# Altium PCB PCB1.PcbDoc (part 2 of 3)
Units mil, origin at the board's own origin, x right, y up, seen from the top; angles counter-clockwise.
Board outline 5995.03 x 3870.03 mil, 2 copper layers (Top Layer, Bottom Layer); 16 components, 23 nets, 121 pads, 0 vias.
Unrouted connection lines stored in the file: 7.
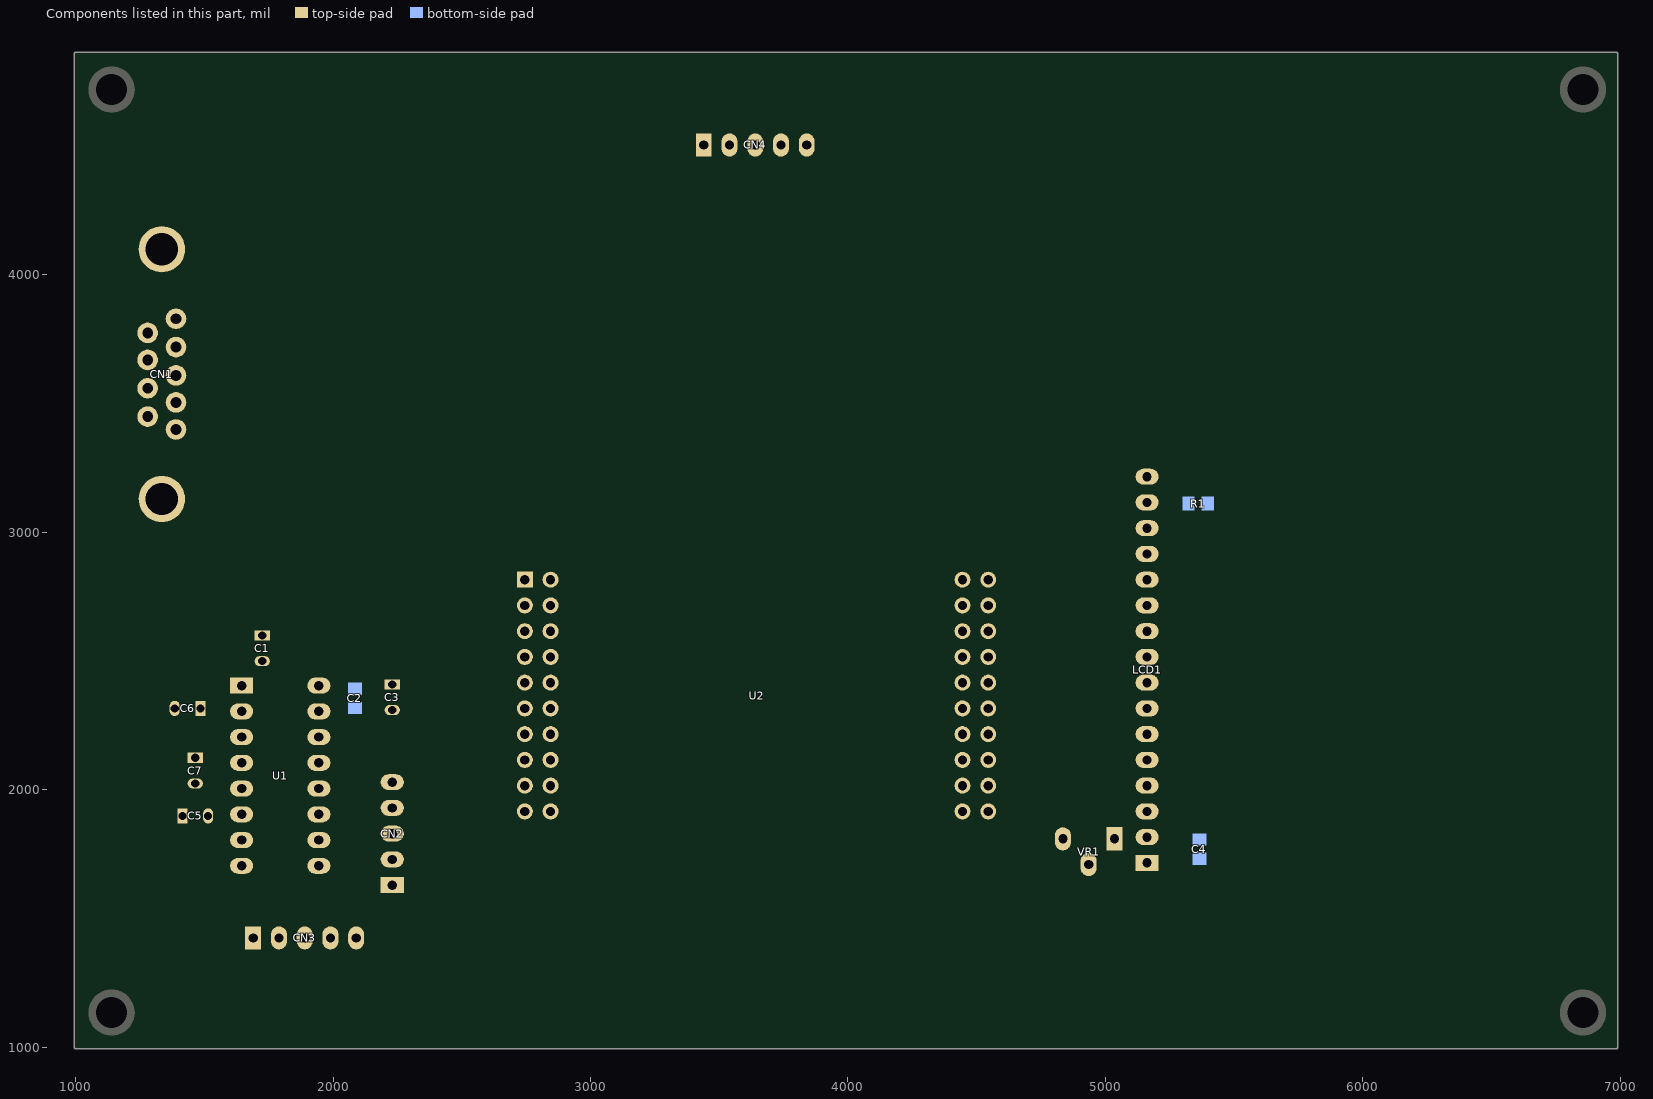
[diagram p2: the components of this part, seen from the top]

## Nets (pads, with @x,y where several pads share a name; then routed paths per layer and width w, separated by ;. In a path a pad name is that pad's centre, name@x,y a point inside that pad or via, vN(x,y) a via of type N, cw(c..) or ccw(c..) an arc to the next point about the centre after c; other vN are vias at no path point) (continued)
copper on no net: (continued)
  Bottom Layer w1: 1727,4165 2162,4165 ; 1727,4166 1944,4166 ; 1727,4167 1942,4167 ; 1727,4168 1940,4168 ; 1727,4169 1938,4169 ; 1727,4170 1937,4170 ; 1727,4171 1935,4171 ; 1727,4172 1933,4172 ; 1727,4173 1931,4173 ; 1727,4174 1930,4174 ; 1727,4175 1928,4175 ; 1727,4176 1926,4176 ; 1727,4177 1925,4177 ; 1727,4178 1923,4178 ; 1727,4179 1921,4179 ; 1727,4180 1919,4180 ; 1727,4181 1918,4181 ; 1727,4182 1916,4182 ; 1727,4183 1914,4183 ; 1727,4184 1912,4184 ; 1727,4185 1911,4185 ; 1727,4186 1909,4186 ; 1727,4187 1907,4187 ; 1727,4188 1905,4188 ; 1727,4189 1904,4189 ; 1727,4190 1902,4190 ; 1727,4191 1900,4191 ; 1727,4192 1899,4192 ; 1727,4193 1897,4193 ; 1727,4194 1895,4194 ; 1727,4195 1893,4195 ; 1727,4196 1892,4196 ; 1727,4197 1890,4197 ; 1727,4198 1888,4198 ; 1727,4199 1886,4199 ; 1727,4200 1885,4200 ; 1727,4201 1883,4201 ; 1727,4202 1881,4202 ; 1727,4203 1879,4203 ; 1727,4204 1878,4204 ; 1727,4205 1876,4205 ; 1727,4206 1874,4206 ; 1727,4207 1873,4207 ; 1727,4208 1871,4208 ; 1727,4209 1869,4209 ; 1727,4210 1867,4210 ; 1727,4211 1866,4211 ; 1727,4212 1864,4212 ; 1727,4213 1862,4213 ; 1727,4214 1860,4214 ; 1727,4215 1859,4215 ; 1727,4216 1857,4216 ; 1727,4217 1855,4217 ; 1727,4218 1854,4218 ; 1727,4219 1852,4219 ; 1727,4220 1850,4220 ; 1727,4221 1848,4221 ; 1727,4222 1847,4222 ; 1727,4223 1845,4223 ; 1727,4224 1843,4224 ; 1727,4225 1841,4225 ; 1727,4226 1840,4226 ; 1727,4227 1838,4227 ; 1727,4228 1837,4228 ; 1727,4229 1837,4229 ; 1727,4230 1837,4230 ; 1727,4231 1837,4231 ; 1727,4232 1837,4232 ; 1727,4233 1837,4233 ; 1727,4234 1837,4234 ; 1727,4235 1837,4235 ; 1727,4236 1837,4236 ; 1727,4237 1837,4237 ; 1727,4238 1837,4238 ; 1727,4239 1837,4239 ; 1727,4240 1837,4240 ; 1727,4241 1837,4241 ; 1727,4242 1837,4242 ; 1727,4243 1837,4243 ; 1727,4244 1837,4244 ; 1727,4245 1837,4245 ; 1727,4246 1837,4246 ; 1727,4247 1837,4247 ; 1727,4248 1837,4248 ; 1727,4249 1837,4249 ; 1727,4250 1837,4250 ; 1727,4251 1837,4251 ; 1727,4252 1837,4252 ; 1727,4253 1837,4253 ; 1727,4254 1837,4254 ; 1727,4255 1837,4255 ; 1727,4256 1837,4256 ; 1727,4257 1837,4257 ; 1727,4258 1837,4258 ; 1727,4259 1837,4259 ; 1727,4260 1837,4260 ; 1727,4261 1837,4261 ; 1727,4262 1837,4262 ; 1727,4263 1837,4263 ; 1727,4264 1837,4264 ; 1727,4265 1837,4265 ; 1727,4266 1837,4266 ; 1727,4267 1837,4267 ; 1727,4268 1837,4268 ; 1727,4269 1837,4269 ; 1727,4270 1837,4270 ; 1727,4271 1837,4271 ; 1727,4272 1837,4272 ; 1727,4273 1837,4273 ; 1727,4274 1837,4274 ; 1727,4275 1837,4275 ; 1727,4276 1837,4276 ; 1727,4277 1837,4277 ; 1727,4278 1837,4278 ; 1727,4279 1837,4279 ; 1727,4280 1837,4280 ; 1727,4281 1837,4281 ; 1727,4282 1837,4282 ; 1727,4283 1837,4283 ; 1727,4284 1837,4284 ; 1727,4285 1837,4285 ; 1727,4286 1837,4286 ; 1727,4287 1837,4287 ; 1727,4288 1837,4288 ; 1727,4289 1837,4289 ; 1727,4290 1837,4290 ; 1728,4164 2162,4164 ; 1729,4291 1837,4291 ; 1730,4163 1943,4163 ; 1730,4292 1837,4292 ; 1732,4162 1941,4162 ; 1732,4293 1837,4293 ; 1733,4161 1939,4161 ; 1734,4294 1837,4294 ; 1735,4160 1938,4160 ; 1735,4295 1837,4295 ; 1737,4159 1936,4159 ; 1737,4296 1837,4296 ; 1739,4158 1934,4158 ; 1739,4297 1837,4297 ; 1740,4157 1932,4157 ; 1741,4298 1837,4298 ; 1742,4156 1931,4156 ; 1742,4299 1837,4299 ; 1744,4155 1929,4155 ; 1744,4300 1837,4300 ; 1746,4154 1927,4154 ; 1746,4301 1837,4301 ; 1747,4153 1925,4153 ; 1748,4302 1837,4302 ; 1749,4152 1924,4152 ; 1749,4303 1837,4303 ; 1751,4151 1922,4151 ; 1751,4304 1837,4304 ; 1753,4150 1920,4150 ; 1753,4305 1837,4305 ; 1754,4149 1918,4149 ; 1754,4306 1837,4306 ; 1756,4148 1917,4148 ; 1756,4307 1837,4307 ; 1758,4147 1915,4147 ; 1758,4308 1837,4308 ; 1759,4146 1913,4146 ; 1760,4309 1837,4309 ; 1761,4145 1912,4145 ; 1761,4310 1837,4310 ; 1763,4144 1910,4144 ; 1763,4311 1837,4311 ; 1765,4143 1908,4143 ; 1765,4312 1837,4312 ; 1766,4142 1906,4142 ; 1767,4313 1837,4313 ; 1768,4141 1905,4141 ; 1768,4314 1837,4314 ; 1770,4140 1903,4140 ; 1770,4315 1837,4315 ; 1772,4139 1901,4139 ; 1772,4316 1837,4316 ; 1773,4138 1899,4138 ; 1774,4317 1837,4317 ; 1775,4137 1898,4137 ; 1775,4318 1837,4318 ; 1777,4136 1896,4136 ; 1777,4319 1837,4319 ; 1779,4135 1894,4135 ; 1779,4320 1837,4320 ; 1780,4134 1892,4134 ; 1780,4321 1837,4321 ; 1782,4133 1891,4133 ; 1782,4322 1837,4322 ; 1784,4132 1889,4132 ; 1784,4323 1837,4323 ; 1785,4131 1887,4131 ; 1786,4324 1837,4324 ; 1787,4130 1886,4130 ; 1787,4325 1837,4325 ; 1789,4129 1884,4129 ; 1789,4326 1837,4326 ; 1791,4128 1882,4128 ; 1791,4327 1837,4327 ; 1792,4127 1880,4127 ; 1793,4328 1837,4328 ; 1794,4126 1879,4126 ; 1794,4329 1837,4329 ; 1796,4125 1877,4125 ; 1796,4330 1837,4330 ; 1798,4124 1875,4124 ; 1798,4331 1837,4331 ; 1799,4123 1873,4123 ; 1800,4332 1837,4332 ; 1801,4122 1872,4122 ; 1801,4333 1837,4333 ; 1803,4121 1870,4121 ; 1803,4334 1837,4334 ; 1804,4120 1868,4120 ; 1805,4335 1837,4335 ; 1806,4119 1866,4119 ; 1806,4336 1837,4336 ; 1808,4118 1865,4118 ; 1808,4337 1837,4337 ; 1810,4117 1863,4117 ; 1810,4338 1837,4338 ; 1811,4116 1861,4116 ; 1812,4339 1837,4339 ; 1813,4115 1860,4115 ; 1813,4340 1837,4340 ; 1815,4114 1858,4114 ; 1815,4341 1837,4341 ; 1817,4113 1856,4113 ; 1817,4342 1837,4342 ; 1818,4112 1854,4112 ; 1819,4343 1837,4343 ; 1820,4111 1853,4111 ; 1820,4344 1837,4344 ; 1822,4110 1851,4110 ; 1822,4345 1837,4345 ; 1824,4109 1849,4109 ; 1824,4346 1837,4346 ; 1825,4108 1847,4108 ; 1825,4347 1837,4347 ; 1827,4107 1846,4107 ; 1827,4348 1837,4348 ; 1829,4106 1844,4106 ; 1829,4349 1837,4349 ; 1830,4105 1842,4105 ; 1831,4350 1837,4350 ; 1832,4104 1840,4104 ; 1832,4351 1837,4351 ; 1834,4103 1839,4103 ; 1834,4352 1837,4352 ; 1836,4102 1837,4102 ; 1836,4353 1838,4353 ; 1836,4354 1839,4354 ; 1836,4355 1841,4355 ; 1836,4356 1843,4356 ; 1836,4357 1844,4357 ; 1836,4358 1846,4358 ; 1836,4359 1848,4359 ; 1836,4360 1850,4360 ; 1836,4361 1851,4361 ; 1836,4362 1853,4362 ; 1836,4363 1855,4363 ; 1836,4364 1857,4364 ; 1836,4365 1858,4365 ; 1836,4366 1860,4366 ; 1836,4367 1862,4367 ; 1836,4368 1864,4368 ; 1836,4369 1865,4369 ; 1836,4370 1867,4370 ; 1836,4371 1869,4371 ; 1836,4372 1870,4372 ; 1836,4373 1872,4373 ; 1836,4374 1874,4374 ; 1836,4375 1876,4375 ; 1836,4376 1877,4376 ; 1836,4377 1879,4377 ; 1836,4378 1881,4378 ; 1836,4379 1883,4379 ; 1836,4380 1884,4380 ; 1836,4381 1886,4381 ; 1836,4382 1888,4382 ; 1836,4383 1889,4383 ; 1836,4384 1891,4384 ; 1836,4385 1893,4385 ; 1836,4386 1895,4386 ; 1836,4387 1896,4387 ; 1836,4388 1898,4388 ; 1836,4389 1900,4389 ; 1836,4390 1902,4390 ; 1836,4391 1903,4391 ; 1836,4392 1905,4392 ; 1836,4393 1907,4393 ; 1836,4394 1909,4394 ; 1836,4395 1910,4395 ; 1836,4396 1912,4396 ; 1836,4397 1914,4397 ; 1836,4398 1915,4398 ; 1836,4399 1917,4399 ; 1836,4400 1919,4400 ; 1836,4401 1921,4401 ; 1836,4402 1922,4402 ; 1836,4403 1924,4403 ; 1836,4404 1926,4404 ; 1836,4405 1928,4405 ; 1836,4406 1929,4406 ; 1836,4407 1931,4407 ; 1836,4408 1933,4408 ; 1836,4409 1935,4409 ; 1836,4410 1936,4410 ; 1836,4411 1938,4411 ; 1836,4412 1940,4412 ; 1836,4413 1941,4413 ; 1836,4414 1943,4414 ; 1836,4415 2054,4415 ; 1836,4416 2054,4416 ; 1836,4417 2054,4417 ; 1836,4418 2054,4418 ; 1836,4419 2054,4419 ; 1836,4420 2054,4420 ; 1836,4421 2054,4421 ; 1836,4422 2054,4422 ; 1836,4423 2054,4423 ; 1836,4424 2054,4424 ; 1836,4425 2054,4425 ; 1836,4426 2054,4426 ; 1836,4427 2054,4427 ; 1836,4428 2054,4428 ; 1836,4429 2054,4429 ; 1836,4430 2054,4430 ; 1836,4431 2054,4431 ; 1836,4432 2054,4432 ; 1836,4433 2054,4433 ; 1836,4434 2054,4434 ; 1836,4435 2054,4435 ; 1836,4436 2054,4436 ; 1836,4437 2054,4437 ; 1836,4438 2054,4438 ; 1836,4439 2054,4439 ; 1836,4440 2054,4440 ; 1836,4441 2054,4441 ; 1836,4442 2054,4442 ; 1836,4443 2054,4443 ; 1836,4444 2054,4444 ; 1836,4445 2054,4445 ; 1836,4446 2054,4446 ; 1836,4447 2054,4447 ; 1836,4448 2054,4448 ; 1836,4449 2054,4449 ; 1836,4450 2054,4450 ; 1836,4451 2054,4451 ; 1836,4452 2054,4452 ; 1836,4453 2054,4453 ; 1836,4454 2054,4454 ; 1836,4455 2054,4455 ; 1836,4456 2054,4456 ; 1836,4457 2054,4457 ; 1836,4458 2054,4458 ; 1836,4459 2054,4459 ; 1836,4460 2054,4460 ; 1836,4461 2054,4461 ; 1836,4462 2054,4462 ; 1836,4463 2054,4463 ; 1836,4464 2054,4464 ; 1836,4465 2054,4465 ; 1836,4466 2054,4466 ; 1836,4467 2054,4467 ; 1836,4468 2054,4468 ; 1836,4469 2054,4469 ; 1836,4470 2054,4470 ; 1836,4471 2054,4471 ; 1836,4472 2054,4472 ; 1836,4473 2054,4473 ; 1836,4474 2054,4474 ; 1836,4475 2054,4475 ; 1836,4476 2054,4476 ; 1836,4477 2054,4477 ; 1836,4478 2054,4478 ; 1837,4479 2053,4479 ; 1839,4480 2051,4480 ; 1840,4481 2049,4481 ; 1842,4482 2048,4482 ; 1844,4483 2046,4483 ; 1846,4484 2044,4484 ; 1847,4485 2042,4485 ; 1849,4486 2041,4486 ; 1851,4487 2039,4487 ; 1853,4488 2037,4488 ; 1854,4489 2036,4489 ; 1856,4490 2034,4490 ; 1858,4491 2032,4491 ; 1860,4492 2030,4492 ; 1861,4493 2029,4493 ; 1863,4494 2027,4494 ; 1865,4273 1886,4273 ; 1865,4274 1887,4274 ; 1865,4275 1887,4275 ; 1865,4495 2025,4495 ; 1866,4276 1888,4276 ; 1866,4354 1889,4354 ; 1866,4496 2023,4496 ; 1867,4228 1874,4228 ; 1867,4229 1874,4229 ; 1867,4230 1874,4230 ; 1867,4231 1874,4231 ; 1867,4232 1874,4232 ; 1867,4233 1874,4233 ; 1867,4234 1874,4234 ; 1867,4235 1874,4235 ; 1867,4236 1874,4236 ; 1867,4237 1874,4237 ; 1867,4238 1874,4238 ; 1867,4239 1874,4239 ; 1867,4240 1874,4240 ; 1867,4241 1874,4241 ; 1867,4242 1874,4242 ; 1867,4243 1874,4243 ; 1867,4244 1874,4244 ; 1867,4245 1874,4245 ; 1867,4246 1874,4246 ; 1867,4247 1881,4247 ; 1867,4248 1880,4248 ; 1867,4249 1880,4249 ; 1867,4250 1880,4250 ; 1867,4251 1880,4251 ; 1867,4252 1879,4252 ; 1867,4253 1879,4253 ; 1867,4254 1879,4254 ; 1867,4255 1878,4255 ; 1867,4256 1878,4256 ; 1867,4257 1878,4257 ; 1867,4258 1878,4258 ; 1867,4277 1888,4277 ; 1867,4278 1889,4278 ; 1867,4353 1890,4353 ; 1868,4259 1877,4259 ; 1868,4279 1889,4279 ; 1868,4352 1890,4352 ; 1868,4497 2022,4497 ; 1869,4280 1890,4280 ; 1869,4281 1891,4281 ; 1869,4351 1891,4351 ; 1870,4282 1891,4282 ; 1870,4350 1892,4350 ; 1870,4498 2020,4498 ; 1871,4283 1892,4283 ; 1871,4284 1892,4284 ; 1871,4349 1893,4349 ; 1872,4285 1893,4285 ; 1872,4286 1893,4286 ; 1872,4348 1894,4348 ; 1872,4499 2018,4499 ; 1873,4287 1894,4287 ; 1873,4346 1896,4346 ; 1873,4347 1895,4347 ; 1873,4500 2016,4500 ; 1874,4288 1895,4288 ; 1874,4289 1895,4289 ; 1874,4345 1897,4345 ; 1875,4243 1882,4243 ; 1875,4244 1881,4244 ; 1875,4245 1881,4245 ; 1875,4246 1881,4246 ; 1875,4290 1896,4290 ; 1875,4344 1898,4344 ; 1875,4501 2015,4501 ; 1876,4239 1889,4239 ; 1876,4240 1882,4240 ; 1876,4241 1882,4241 ; 1876,4242 1882,4242 ; 1876,4291 1896,4291 ; 1876,4292 1897,4292 ; 1876,4343 1899,4343 ; 1877,4235 1888,4235 ; 1877,4236 1888,4236 ; 1877,4237 1888,4237 ; 1877,4238 1889,4238 ; 1877,4293 1897,4293 ; 1877,4342 1899,4342 ; 1877,4502 2013,4502 ; 1878,4231 1887,4231 ; 1878,4232 1887,4232 ; 1878,4233 1887,4233 ; 1878,4234 1888,4234 ; 1878,4294 1898,4294 ; 1878,4295 1899,4295 ; 1878,4341 1900,4341 ; 1879,4228 1886,4228 ; 1879,4229 1886,4229 ; 1879,4230 1887,4230 ; 1879,4296 1899,4296 ; 1879,4340 1901,4340 ; 1879,4503 2011,4503 ; 1880,4297 1900,4297 ; 1880,4298 1900,4298 ; 1880,4339 1902,4339 ; 1880,4504 2010,4504 ; 1881,4299 1901,4299 ; 1881,4300 1902,4300 ; 1881,4338 1903,4338 ; 1882,4301 1902,4301 ; 1882,4337 1904,4337 ; 1882,4505 2008,4505 ; 1883,4240 1889,4240 ; 1883,4241 1889,4241 ; 1883,4242 1890,4242 ; 1883,4302 1903,4302 ; 1883,4303 1903,4303 ; 1883,4336 1905,4336 ; 1884,4243 1890,4243 ; 1884,4244 1890,4244 ; 1884,4245 1890,4245 ; 1884,4246 1890,4246 ; 1884,4304 1904,4304 ; 1884,4335 1906,4335 ; 1884,4506 2006,4506 ; 1885,4247 1898,4247 ; 1885,4248 1898,4248 ; 1885,4249 1898,4249 ; 1885,4250 1898,4250 ; 1885,4305 1904,4305 ; 1885,4306 1905,4306 ; 1885,4334 1907,4334 ; 1886,4251 1898,4251 ; 1886,4252 1898,4252 ; 1886,4253 1898,4253 ; 1886,4254 1898,4254 ; 1886,4307 1906,4307 ; 1886,4333 1908,4333 ; 1886,4507 2004,4507 ; 1887,4255 1898,4255 ; 1887,4256 1898,4256 ; 1887,4257 1898,4257 ; 1887,4308 1906,4308 ; 1887,4309 1907,4309 ; 1887,4332 1908,4332 ; 1887,4508 2003,4508 ; 1888,4258 1898,4258 ; 1888,4259 1898,4259 ; 1888,4310 1907,4310 ; 1888,4311 1937,4311 ; 1888,4331 1909,4331 ; 1889,4312 1937,4312 ; 1889,4330 1910,4330 ; 1889,4509 2001,4509 ; 1890,4313 1937,4313 ; 1890,4314 1937,4314 ; 1890,4329 1911,4329 ; 1891,4228 1898,4228 ; 1891,4229 1898,4229 ; 1891,4230 1898,4230 ; 1891,4231 1898,4231 ; 1891,4232 1898,4232 ; 1891,4233 1898,4233 ; 1891,4234 1898,4234 ; 1891,4235 1898,4235 ; 1891,4236 1898,4236 ; 1891,4237 1898,4237 ; 1891,4238 1898,4238 ; 1891,4239 1898,4239 ; 1891,4240 1898,4240 ; 1891,4241 1898,4241 ; 1891,4242 1898,4242 ; 1891,4243 1898,4243 ; 1891,4244 1898,4244 ; 1891,4245 1898,4245 ; 1891,4246 1898,4246 ; 1891,4315 1937,4315 ; 1891,4328 1912,4328 ; 1891,4510 1999,4510 ; 1892,4316 1937,4316 ; 1892,4317 1937,4317 ; 1892,4326 1914,4326 ; 1892,4327 1913,4327 ; 1892,4511 1997,4511 ; 1893,4318 1937,4318 ; 1893,4325 1915,4325 ; 1894,4319 1937,4319 ; 1894,4320 1919,4320 ; 1894,4324 1916,4324 ; 1894,4512 1996,4512 ; 1895,4321 1918,4321 ; 1895,4323 1917,4323 ; 1896,4322 1918,4322 ; 1896,4513 1994,4513 ; 1898,4514 1992,4514 ; 1899,4515 1991,4515 ; 1901,4516 1989,4516 ; 1902,4237 1910,4237 ; 1903,4235 1911,4235 ; 1903,4236 1910,4236 ; 1903,4238 1910,4238 ; 1903,4250 1910,4250 ; 1903,4251 1910,4251 ; 1903,4252 1911,4252 ; 1903,4253 1913,4253 ; 1903,4517 1987,4517 ; 1904,4233 1927,4233 ; 1904,4234 1913,4234 ; 1904,4254 1927,4254 ; 1905,4232 1926,4232 ; 1905,4255 1926,4255 ; 1905,4256 1925,4256 ; 1905,4518 1985,4518 ; 1906,4231 1925,4231 ; 1906,4239 1909,4239 ; 1906,4257 1924,4257 ; 1906,4519 1984,4519 ; 1907,4230 1924,4230 ; 1907,4249 1909,4249 ; 1908,4229 1923,4229 ; 1908,4258 1922,4258 ; 1908,4310 1937,4310 ; 1908,4520 1982,4520 ; 1909,4309 1937,4309 ; 1910,4228 1921,4228 ; 1910,4259 1920,4259 ; 1910,4308 1937,4308 ; 1910,4521 1980,4521 ; 1911,4307 1937,4307 ; 1911,4522 1978,4522 ; 1912,4306 1937,4306 ; 1913,4305 1937,4305 ; 1913,4523 1977,4523 ; 1914,4304 1937,4304 ; 1915,4303 1937,4303 ; 1915,4524 1975,4524 ; 1916,4302 1937,4302 ; 1917,4301 1937,4301 ; 1917,4525 1973,4525 ; 1918,4253 1928,4253 ; 1918,4299 1937,4299 ; 1918,4300 1937,4300 ; 1918,4526 1971,4526 ; 1919,4234 1928,4234 ; 1919,4298 1937,4298 ; 1920,4235 1928,4235 ; 1920,4252 1928,4252 ; 1920,4273 1937,4273 ; 1920,4274 1937,4274 ; 1920,4275 1937,4275 ; 1920,4276 1937,4276 ; 1920,4277 1937,4277 ; 1920,4278 1937,4278 ; 1920,4279 1937,4279 ; 1920,4280 1937,4280 ; 1920,4281 1937,4281 ; 1920,4282 1937,4282 ; 1920,4283 1937,4283 ; 1920,4284 1937,4284 ; 1920,4285 1937,4285 ; 1920,4286 1937,4286 ; 1920,4287 1937,4287 ; 1920,4288 1937,4288 ; 1920,4289 1937,4289 ; 1920,4290 1937,4290 ; 1920,4291 1937,4291 ; 1920,4292 1937,4292 ; 1920,4293 1937,4293 ; 1920,4294 1937,4294 ; 1920,4295 1937,4295 ; 1920,4296 1937,4296 ; 1920,4297 1937,4297 ; 1920,4320 1937,4320 ; 1920,4321 1937,4321 ; 1920,4322 1937,4322 ; 1920,4323 1937,4323 ; 1920,4324 1937,4324 ; 1920,4325 1937,4325 ; 1920,4326 1937,4326 ; 1920,4327 1937,4327 ; 1920,4328 1937,4328 ; 1920,4329 1937,4329 ; 1920,4330 1937,4330 ; 1920,4331 1937,4331 ; 1920,4332 1937,4332 ; 1920,4333 1937,4333 ; 1920,4334 1937,4334 ; 1920,4335 1937,4335 ; 1920,4336 1937,4336 ; 1920,4337 1937,4337 ; 1920,4338 1937,4338 ; 1920,4339 1937,4339 ; 1920,4340 1937,4340 ; 1920,4341 1937,4341 ; 1920,4342 1937,4342 ; 1920,4343 1937,4343 ; 1920,4344 1937,4344 ; 1920,4345 1937,4345 ; 1920,4346 1937,4346 ; 1920,4347 1937,4347 ; 1920,4348 1937,4348 ; 1920,4349 1937,4349 ; 1920,4350 1937,4350 ; 1920,4351 1937,4351 ; 1920,4352 1937,4352 ; 1920,4353 1937,4353 ; 1920,4354 1937,4354 ; 1920,4527 1970,4527 ; 1921,4236 1929,4236 ; 1921,4251 1929,4251 ; 1922,4237 1929,4237 ; 1922,4238 1929,4238 ; 1922,4239 1930,4239 ; 1922,4240 1930,4240 ; 1922,4247 1930,4247 ; 1922,4248 1930,4248 ; 1922,4249 1929,4249 ; 1922,4250 1929,4250 ; 1922,4528 1968,4528 ; 1923,4241 1930,4241 ; 1923,4242 1930,4242 ; 1923,4243 1930,4243 ; 1923,4244 1930,4244 ; 1923,4245 1930,4245 ; 1923,4246 1930,4246 ; 1924,4529 1966,4529 ; 1925,4530 1965,4530 ; 1927,4531 1963,4531 ; 1929,4532 1961,4532 ; 1931,4533 1959,4533 ; 1932,4534 1958,4534 ; 1934,4229 1942,4229 ; 1934,4230 1942,4230 ; 1934,4231 1942,4231 ; 1934,4232 1942,4232 ; 1934,4233 1942,4233 ; 1934,4234 1942,4234 ; 1934,4235 1942,4235 ; 1934,4236 1942,4236 ; 1934,4237 1942,4237 ; 1934,4238 1942,4238 ; 1934,4239 1942,4239 ; 1934,4240 1941,4240 ; 1934,4241 1942,4241 ; 1934,4242 1960,4242 ; 1934,4243 1960,4243 ; 1934,4244 1960,4244 ; 1934,4245 1960,4245 ; 1934,4246 1960,4246 ; 1934,4247 1960,4247 ; 1934,4248 1941,4248 ; 1934,4249 1942,4249 ; 1934,4250 1942,4250 ; 1934,4251 1942,4251 ; 1934,4252 1942,4252 ; 1934,4253 1942,4253 ; 1934,4254 1942,4254 ; 1934,4255 1942,4255 ; 1934,4256 1942,4256 ; 1934,4257 1942,4257 ; 1934,4258 1942,4258 ; 1934,4535 1956,4535 ; 1935,4228 1941,4228 ; 1935,4259 1941,4259 ; 1936,4536 1954,4536 ; 1937,4537 1952,4537 ; 1939,4538 1951,4538 ; 1941,4539 1949,4539 ; 1943,4540 1947,4540 ; 1944,4541 1946,4541 ; 1946,4166 2162,4166 ; 1947,4163 2160,4163 ; 1947,4414 2054,4414 ; 1948,4167 2162,4167 ; 1948,4413 2054,4413 ; 1949,4162 2158,4162 ; 1950,4168 2162,4168 ; 1950,4292 1969,4292 ; 1950,4293 1968,4293 ; 1950,4294 1968,4294 ; 1950,4295 1968,4295 ; 1950,4296 1968,4296 ; 1950,4297 1967,4297 ; 1950,4298 1967,4298 ; 1950,4299 1968,4299 ; 1950,4300 1968,4300 ; 1950,4301 1968,4301 ; 1950,4412 2054,4412 ; 1951,4161 2156,4161 ; 1951,4169 2162,4169 ; 1951,4288 1974,4288 ; 1951,4289 1972,4289 ; 1951,4290 1970,4290 ; 1951,4291 1969,4291 ; 1951,4302 1968,4302 ; 1951,4303 1969,4303 ; 1951,4304 1970,4304 ; 1952,4160 2155,4160 ; 1952,4286 2018,4286 ; 1952,4287 2018,4287 ; 1952,4305 1971,4305 ; 1952,4306 1972,4306 ; 1952,4411 2054,4411 ; 1953,4170 2162,4170 ; 1953,4228 1960,4228 ; 1953,4229 1960,4229 ; 1953,4230 1960,4230 ; 1953,4231 1960,4231 ; 1953,4232 1960,4232 ; 1953,4233 1960,4233 ; 1953,4234 1960,4234 ; 1953,4235 1960,4235 ; 1953,4236 1960,4236 ; 1953,4237 1960,4237 ; 1953,4238 1960,4238 ; 1953,4239 1960,4239 ; 1953,4240 1960,4240 ; 1953,4241 1960,4241 ; 1953,4248 1960,4248 ; 1953,4249 1960,4249 ; 1953,4250 1960,4250 ; 1953,4251 1960,4251 ; 1953,4252 1960,4252 ; 1953,4253 1960,4253 ; 1953,4254 1960,4254 ; 1953,4255 1960,4255 ; 1953,4256 1960,4256 ; 1953,4257 1960,4257 ; 1953,4258 1960,4258 ; 1953,4259 1960,4259 ; 1953,4284 2018,4284 ; 1953,4285 2018,4285 ; 1953,4307 1975,4307 ; 1953,4308 2018,4308 ; 1954,4159 2153,4159 ; 1954,4283 2018,4283 ; 1954,4309 2018,4309 ; 1954,4329 1971,4329 ; 1954,4330 1970,4330 ; 1954,4331 1970,4331 ; 1954,4332 1970,4332 ; 1954,4333 1970,4333 ; 1954,4334 1971,4334 ; 1954,4335 1971,4335 ; 1954,4336 1971,4336 ; 1954,4337 1972,4337 ; 1954,4338 1973,4338 ; 1954,4410 2054,4410 ; 1955,4171 2162,4171 ; 1955,4281 2018,4281 ; 1955,4282 2018,4282 ; 1955,4310 2018,4310 ; 1955,4326 1972,4326 ; 1955,4327 1971,4327 ; 1955,4328 1971,4328 ; 1955,4339 1975,4339 ; 1955,4340 1979,4340 ; 1955,4341 2018,4341 ; 1955,4409 2054,4409 ; 1956,4158 2151,4158 ; 1956,4280 2018,4280 ; 1956,4311 2018,4311 ; 1956,4324 1974,4324 ; 1956,4325 1973,4325 ; 1956,4342 2018,4342 ; 1956,4343 2018,4343 ; 1957,4172 2162,4172 ; 1957,4279 2018,4279 ; 1957,4312 2018,4312 ; 1957,4323 1977,4323 ; 1957,4344 2018,4344 ; 1957,4345 2018,4345 ; 1957,4408 2054,4408 ; 1958,4157 2149,4157 ; 1958,4173 2162,4173 ; 1958,4278 2018,4278 ; 1958,4313 2018,4313 ; 1958,4321 2018,4321 ; 1958,4322 2018,4322 ; 1958,4346 2018,4346 ; 1959,4156 2148,4156 ; 1959,4320 2018,4320 ; 1959,4347 2018,4347 ; 1959,4407 2054,4407 ; 1960,4174 2162,4174 ; 1960,4277 2018,4277 ; 1960,4314 2018,4314 ; 1960,4319 2018,4319 ; 1960,4348 2018,4348 ; 1961,4155 2146,4155 ; 1961,4276 2018,4276 ; 1961,4315 2018,4315 ; 1961,4349 2018,4349 ; 1961,4406 2054,4406 ; 1962,4175 2162,4175 ; 1962,4318 2018,4318 ; 1962,4350 2018,4350 ; 1962,4405 2054,4405 ; 1963,4154 2144,4154 ; 1963,4275 2018,4275 ; 1963,4317 2018,4317 ; 1964,4153 2143,4153 ; 1964,4176 2162,4176 ; 1964,4316 2018,4316 ; 1964,4351 2018,4351 ; 1964,4404 2054,4404 ; 1965,4177 2162,4177 ; 1965,4228 1972,4228 ; 1965,4229 1972,4229 ; 1965,4230 1972,4230 ; 1965,4231 1972,4231 ; 1965,4232 1972,4232 ; 1965,4233 1972,4233 ; 1965,4234 1972,4234 ; 1965,4352 2018,4352 ; 1966,4152 2141,4152 ; 1966,4274 2018,4274 ; 1966,4403 2054,4403 ; 1967,4178 2162,4178 ; 1967,4402 2054,4402 ; 1968,4151 2139,4151 ; 1968,4353 2018,4353 ; 1969,4179 2162,4179 ; 1969,4401 2054,4401 ; 1970,4150 2137,4150 ; 1970,4180 2162,4180 ; 1971,4149 2136,4149 ; 1971,4245 1995,4245 ; 1971,4246 1980,4246 ; 1971,4247 1979,4247 ; 1971,4248 1978,4248 ; 1971,4249 1978,4249 ; 1971,4250 1978,4250 ; 1971,4251 1978,4251 ; 1971,4252 1979,4252 ; 1971,4253 1981,4253 ; 1971,4400 2054,4400 ; 1972,4181 2162,4181 ; 1972,4244 1995,4244 ; 1972,4254 1995,4254 ; 1972,4255 1995,4255 ; 1972,4273 2017,4273 ; 1972,4354 2017,4354 ; 1973,4148 2134,4148 ; 1973,4243 1995,4243 ; 1973,4256 1995,4256 ; 1973,4399 2054,4399 ; 1974,4182 2162,4182 ; 1974,4242 1995,4242 ; 1974,4257 1995,4257 ; 1974,4398 2054,4398 ; 1975,4147 2132,4147 ; 1975,4241 1995,4241 ; 1975,4258 1995,4258 ; 1976,4183 2162,4183 ; 1976,4397 2054,4397 ; 1977,4146 2130,4146 ; 1977,4184 2162,4184 ; 1977,4240 1995,4240 ; 1978,4145 2129,4145 ; 1978,4259 1995,4259 ; 1978,4396 2054,4396 ; 1979,4185 2162,4185 ; 1980,4144 2127,4144 ; 1980,4395 2054,4395 ; 1981,4186 2162,4186 ; 1981,4394 2054,4394 ; 1982,4143 2125,4143 ; 1983,4142 2123,4142 ; 1983,4187 2162,4187 ; 1983,4393 2054,4393 ; 1984,4188 2162,4188 ; 1985,4141 2122,4141 ; 1985,4392 2054,4392 ; 1986,4189 2162,4189 ; 1986,4391 2054,4391 ; 1987,4140 2120,4140 ; 1988,4190 2162,4190 ; 1988,4228 1995,4228 ; 1988,4229 1995,4229 ; 1988,4230 1995,4230 ; 1988,4231 1995,4231 ; 1988,4232 1995,4232 ; 1988,4233 1995,4233 ; 1988,4234 1995,4234 ; 1988,4235 1995,4235 ; 1988,4236 1995,4236 ; 1988,4237 1995,4237 ; 1988,4238 1995,4238 ; 1988,4239 1995,4239 ; 1988,4246 1995,4246 ; 1988,4247 1995,4247 ; 1988,4248 1995,4248 ; 1988,4249 1995,4249 ; 1988,4250 1995,4250 ; 1988,4251 1995,4251 ; 1988,4252 1995,4252 ; 1988,4253 1995,4253 ; 1988,4390 2054,4390 ; 1989,4139 2118,4139 ; 1990,4138 2117,4138 ; 1990,4191 2162,4191 ; 1990,4389 2054,4389 ; 1991,4192 2162,4192 ; 1992,4137 2115,4137 ; 1992,4388 2054,4388 ; 1993,4193 2162,4193 ; 1993,4387 2054,4387 ; 1994,4136 2113,4136 ; 1995,4194 2162,4194 ; 1995,4386 2054,4386 ; 1996,4135 2111,4135 ; 1996,4195 2162,4195 ; 1997,4134 2110,4134 ; 1997,4385 2054,4385 ; 1998,4196 2162,4196 ; 1998,4254 2023,4254 ; 1998,4255 2024,4255 ; 1998,4256 2024,4256 ; 1998,4257 2024,4257 ; 1998,4258 2024,4258 ; 1998,4259 2023,4259 ; 1999,4133 2108,4133 ; 1999,4384 2054,4384 ; 2000,4197 2162,4197 ; 2000,4383 2054,4383 ; 2001,4132 2106,4132 ; 2001,4288 2018,4288 ; 2001,4289 2018,4289 ; 2001,4290 2018,4290 ; 2001,4291 2018,4291 ; 2001,4292 2018,4292 ; 2001,4293 2018,4293 ; 2001,4294 2018,4294 ; 2001,4295 2018,4295 ; 2001,4296 2018,4296 ; 2001,4297 2018,4297 ; 2001,4298 2018,4298 ; 2001,4299 2018,4299 ; 2001,4300 2018,4300 ; 2001,4301 2018,4301 ; 2001,4302 2018,4302 ; 2001,4303 2018,4303 ; 2001,4304 2018,4304 ; 2001,4305 2018,4305 ; 2001,4306 2018,4306 ; 2001,4307 2018,4307 ; 2001,4323 2018,4323 ; 2001,4324 2018,4324 ; 2001,4325 2018,4325 ; 2001,4326 2018,4326 ; 2001,4327 2018,4327 ; 2001,4328 2018,4328 ; 2001,4329 2018,4329 ; 2001,4330 2018,4330 ; 2001,4331 2018,4331 ; 2001,4332 2018,4332 ; 2001,4333 2018,4333 ; 2001,4334 2018,4334 ; 2001,4335 2018,4335 ; 2001,4336 2018,4336 ; 2001,4337 2018,4337 ; 2001,4338 2018,4338 ; 2001,4339 2018,4339 ; 2001,4340 2018,4340 ; 2002,4198 2162,4198 ; 2002,4382 2054,4382 ; 2003,4131 2104,4131 ; 2003,4199 2162,4199 ; 2004,4130 2103,4130 ; 2004,4381 2054,4381 ; 2005,4200 2162,4200 ; 2006,4129 2101,4129 ; 2006,4380 2054,4380 ; 2007,4201 2162,4201 ; 2007,4229 2014,4229 ; 2007,4230 2014,4230 ; 2007,4231 2014,4231 ; 2007,4232 2014,4232 ; 2007,4233 2014,4233 ; 2007,4234 2014,4234 ; 2007,4235 2014,4235 ; 2007,4236 2014,4236 ; 2007,4237 2014,4237 ; 2007,4238 2014,4238 ; 2007,4239 2014,4239 ; 2007,4240 2014,4240 ; 2007,4241 2014,4241 ; 2007,4242 2014,4242 ; 2007,4243 2014,4243 ; 2007,4244 2014,4244 ; 2007,4245 2014,4245 ; 2007,4246 2014,4246 ; 2007,4247 2014,4247 ; 2007,4248 2014,4248 ; 2007,4249 2014,4249 ; 2007,4250 2014,4250 ; 2007,4251 2014,4251 ; 2007,4252 2014,4252 ; 2007,4253 2014,4253 ; 2007,4379 2054,4379 ; 2008,4128 2099,4128 ; 2008,4228 2014,4228 ; 2009,4127 2098,4127 ; 2009,4202 2162,4202 ; 2009,4378 2054,4378 ; 2010,4203 2162,4203 ; 2011,4126 2096,4126 ; 2011,4377 2054,4377 ; 2012,4204 2162,4204 ; 2012,4376 2054,4376 ; 2013,4125 2094,4125 ; 2014,4205 2162,4205 ; 2014,4375 2054,4375 ; 2015,4124 2092,4124 ; 2016,4123 2091,4123 ; 2016,4206 2162,4206 ; 2016,4374 2054,4374 ; 2017,4207 2162,4207 ; 2018,4122 2089,4122 ; 2018,4373 2054,4373 ; 2019,4208 2162,4208 ; 2019,4372 2054,4372 ; 2020,4121 2087,4121 ; 2021,4209 2162,4209 ; 2021,4371 2054,4371 ; 2022,4120 2085,4120 ; 2022,4210 2162,4210 ; 2023,4119 2084,4119 ; 2023,4370 2054,4370 ; 2024,4211 2162,4211 ; 2025,4118 2082,4118 ; 2025,4369 2054,4369 ; 2026,4212 2162,4212 ; 2026,4368 2054,4368 ; 2027,4117 2080,4117 ; 2028,4213 2162,4213 ; 2028,4367 2054,4367 ; 2029,4116 2078,4116 ; 2029,4214 2162,4214 ; 2030,4115 2077,4115 ; 2030,4366 2054,4366 ; 2031,4215 2162,4215 ; 2032,4114 2075,4114 ; 2032,4365 2054,4365 ; 2033,4216 2162,4216 ; 2033,4364 2054,4364 ; 2034,4113 2073,4113 ; 2035,4112 2072,4112 ; 2035,4217 2162,4217 ; 2035,4363 2054,4363 ; 2036,4218 2162,4218 ; 2037,4111 2070,4111 ; 2037,4362 2054,4362 ; 2038,4219 2162,4219 ; 2038,4361 2054,4361 ; 2039,4110 2068,4110 ; 2040,4220 2162,4220 ; 2040,4360 2054,4360 ; 2041,4109 2066,4109 ; 2042,4108 2065,4108 ; 2042,4221 2162,4221 ; 2042,4359 2054,4359 ; 2043,4222 2162,4222 ; 2044,4107 2063,4107 ; 2044,4358 2054,4358 ; 2045,4223 2162,4223 ; 2045,4357 2054,4357 ; 2046,4106 2061,4106 ; 2047,4224 2162,4224 ; 2047,4356 2054,4356 ; 2048,4105 2059,4105 ; 2048,4225 2162,4225 ; 2049,4104 2058,4104 ; 2049,4355 2054,4355 ; 2050,4226 2162,4226 ; 2051,4103 2056,4103 ; 2051,4354 2054,4354 ; 2052,4227 2162,4227 ; 2052,4353 2054,4353 ; 2053,4102 2054,4102 ; 2053,4228 2162,4228 ; 2053,4229 2162,4229 ; 2053,4230 2162,4230 ; 2053,4231 2162,4231 ; 2053,4232 2162,4232 ; 2053,4233 2162,4233 ; 2053,4234 2162,4234 ; 2053,4235 2162,4235 ; 2053,4236 2162,4236 ; 2053,4237 2162,4237 ; 2053,4238 2162,4238 ; 2053,4239 2162,4239 ; 2053,4240 2162,4240 ; 2053,4241 2162,4241 ; 2053,4242 2162,4242 ; 2053,4243 2162,4243 ; 2053,4244 2162,4244 ; 2053,4245 2162,4245 ; 2053,4246 2162,4246 ; 2053,4247 2162,4247 ; 2053,4248 2162,4248 ; 2053,4249 2162,4249 ; 2053,4250 2162,4250 ; 2053,4251 2162,4251 ; 2053,4252 2162,4252 ; 2053,4253 2162,4253 ; 2053,4254 2162,4254 ; 2053,4255 2162,4255 ; 2053,4256 2162,4256 ; 2053,4257 2162,4257 ; 2053,4258 2162,4258 ; 2053,4259 2162,4259 ; 2053,4260 2162,4260 ; 2053,4261 2162,4261 ; 2053,4262 2162,4262 ; 2053,4263 2162,4263 ; 2053,4264 2162,4264 ; 2053,4265 2162,4265 ; 2053,4266 2162,4266 ; 2053,4267 2162,4267 ; 2053,4268 2162,4268 ; 2053,4269 2162,4269 ; 2053,4270 2162,4270 ; 2053,4271 2162,4271 ; 2053,4272 2162,4272 ; 2053,4273 2162,4273 ; 2053,4274 2162,4274 ; 2053,4275 2162,4275 ; 2053,4276 2162,4276 ; 2053,4277 2162,4277 ; 2053,4278 2162,4278 ; 2053,4279 2162,4279 ; 2053,4280 2162,4280 ; 2053,4281 2162,4281 ; 2053,4282 2162,4282 ; 2053,4283 2162,4283 ; 2053,4284 2162,4284 ; 2053,4285 2162,4285 ; 2053,4286 2162,4286 ; 2053,4287 2162,4287 ; 2053,4288 2162,4288 ; 2053,4289 2162,4289 ; 2053,4290 2162,4290 ; 2053,4291 2161,4291 ; 2053,4292 2160,4292 ; 2053,4293 2158,4293 ; 2053,4294 2156,4294 ; 2053,4295 2154,4295 ; 2053,4296 2153,4296 ; 2053,4297 2151,4297 ; 2053,4298 2149,4298 ; 2053,4299 2147,4299 ; 2053,4300 2146,4300 ; 2053,4301 2144,4301 ; 2053,4302 2142,4302 ; 2053,4303 2141,4303 ; 2053,4304 2139,4304 ; 2053,4305 2137,4305 ; 2053,4306 2135,4306 ; 2053,4307 2134,4307 ; 2053,4308 2132,4308 ; 2053,4309 2130,4309 ; 2053,4310 2128,4310 ; 2053,4311 2127,4311 ; 2053,4312 2125,4312 ; 2053,4313 2123,4313 ; 2053,4314 2121,4314 ; 2053,4315 2120,4315 ; 2053,4316 2118,4316 ; 2053,4317 2116,4317 ; 2053,4318 2115,4318 ; 2053,4319 2113,4319 ; 2053,4320 2111,4320 ; 2053,4321 2109,4321 ; 2053,4322 2108,4322 ; 2053,4323 2106,4323 ; 2053,4324 2104,4324 ; 2053,4325 2102,4325 ; 2053,4326 2101,4326 ; 2053,4327 2099,4327 ; 2053,4328 2097,4328 ; 2053,4329 2095,4329 ; 2053,4330 2094,4330 ; 2053,4331 2092,4331 ; 2053,4332 2090,4332 ; 2053,4333 2089,4333 ; 2053,4334 2087,4334 ; 2053,4335 2085,4335 ; 2053,4336 2083,4336 ; 2053,4337 2082,4337 ; 2053,4338 2080,4338 ; 2053,4339 2078,4339 ; 2053,4340 2076,4340 ; 2053,4341 2075,4341 ; 2053,4342 2073,4342 ; 2053,4343 2071,4343 ; 2053,4344 2070,4344 ; 2053,4345 2068,4345 ; 2053,4346 2066,4346 ; 2053,4347 2064,4347 ; 2053,4348 2063,4348 ; 2053,4349 2061,4349 ; 2053,4350 2059,4350 ; 2053,4351 2057,4351 ; 2053,4352 2056,4352 ; 6584,3319 6584,3856 ; 6585,3319 6585,3862 ; 6586,3319 6586,3865 ; 6587,3319 6587,3868 ; 6588,3319 6588,3871 ; 6589,3319 6589,3873 ; 6590,3319 6590,3875 ; 6591,3319 6591,3877 ; 6592,3319 6592,3879 ; 6593,3319 6593,3881 ; 6594,3319 6594,3882 ; 6595,3319 6595,3884 ; 6596,3319 6596,3885 ; 6597,3319 6597,3886 ; 6598,3319 6598,3887 ; 6599,3319 6599,3889 ; 6600,3319 6600,3890 ; 6601,3319 6601,3891 ; 6602,3319 6602,3892 ; 6603,3319 6603,3893 ; 6604,3319 6604,3894 ; 6605,3319 6605,3894 ; 6606,3319 6606,3895 ; 6607,3319 6607,3896 ; 6608,3319 6608,3897 ; 6609,3319 6609,3898 ; 6610,3319 6610,3898 ; 6611,3319 6611,3899 ; 6612,3319 6612,3900 ; 6613,3319 6613,3901 ; 6614,3319 6614,3901 ; 6615,3319 6615,3902 ; 6616,3319 6616,3902 ; 6617,3319 6617,3903 ; 6618,3319 6618,3904 ; 6619,3319 6619,3904 ; 6620,3319 6620,3904 ; 6621,3319 6621,3905 ; 6622,3319 6622,3905 ; 6623,3319 6623,3906 ; 6624,3319 6624,3906 ; 6625,3319 6625,3907 ; 6626,3319 6626,3907 ; 6627,3319 6627,3907 ; 6628,3319 6628,3908 ; 6629,3319 6629,3908 ; 6630,3319 6630,3908 ; 6631,3319 6631,3908 ; 6632,3319 6632,3909 ; 6633,3319 6633,3695 ; 6633,3726 6633,3764 ; 6633,3785 6633,3909 ; 6634,3319 6634,3650 ; 6634,3681 6634,3696 ; 6634,3727 6634,3764 ; 6634,3791 6634,3909 ; 6635,3319 6635,3651 ; 6635,3681 6635,3696 ; 6635,3727 6635,3764 ; 6635,3794 6635,3909 ; 6636,3319 6636,3651 ; 6636,3682 6636,3696 ; 6636,3727 6636,3764 ; 6636,3797 6636,3909 ; 6637,3319 6637,3651 ; 6637,3682 6637,3696 ; 6637,3727 6637,3764 ; 6637,3799 6637,3909 ; 6638,3319 6638,3651 ; 6638,3682 6638,3697 ; 6638,3728 6638,3764 ; 6638,3801 6638,3909 ; 6639,3319 6639,3652 ; 6639,3682 6639,3697 ; 6639,3728 6639,3764 ; 6639,3803 6639,3909 ; 6640,3319 6640,3652 ; 6640,3683 6640,3697 ; 6640,3728 6640,3763 ; 6640,3804 6640,3909 ; 6641,3319 6641,3652 ; 6641,3683 6641,3697 ; 6641,3728 6641,3763 ; 6641,3806 6641,3909 ; 6642,3319 6642,3652 ; 6642,3683 6642,3698 ; 6642,3729 6642,3763 ; 6642,3807 6642,3909 ; 6643,3319 6643,3653 ; 6643,3683 6643,3698 ; 6643,3729 6643,3763 ; 6643,3808 6643,3909 ; 6644,3319 6644,3653 ; 6644,3684 6644,3698 ; 6644,3729 6644,3763 ; 6644,3809 6644,3909 ; 6645,3319 6645,3653 ; 6645,3684 6645,3698 ; 6645,3729 6645,3763 ; 6645,3810 6645,3909 ; 6646,3319 6646,3653 ; 6646,3684 6646,3699 ; 6646,3730 6646,3763 ; 6646,3811 6646,3909 ; 6647,3319 6647,3654 ; 6647,3684 6647,3699 ; 6647,3730 6647,3763 ; 6647,3812 6647,3909 ; 6648,3319 6648,3654 ; 6648,3685 6648,3699 ; 6648,3730 6648,3763 ; 6648,3813 6648,3909 ; 6649,3319 6649,3654 ; 6649,3685 6649,3699 ; 6649,3730 6649,3763 ; 6649,3814 6649,3909 ; 6650,3319 6650,3655 ; 6650,3685 6650,3700 ; 6650,3731 6650,3763 ; 6650,3815 6650,3909 ; 6651,3319 6651,3655 ; 6651,3685 6651,3700 ; 6651,3731 6651,3763 ; 6651,3815 6651,3909 ; 6652,3319 6652,3655 ; 6652,3686 6652,3700 ; 6652,3731 6652,3763 ; 6652,3816 6652,3909 ; 6653,3319 6653,3655 ; 6653,3686 6653,3700 ; 6653,3731 6653,3763 ; 6653,3817 6653,3909 ; 6654,3319 6654,3656 ; 6654,3686 6654,3701 ; 6654,3731 6654,3763 ; 6654,3817 6654,3909 ; 6655,3319 6655,3656 ; 6655,3686 6655,3701 ; 6655,3732 6655,3763 ; 6655,3818 6655,3909 ; 6656,3319 6656,3656 ; 6656,3687 6656,3701 ; 6656,3732 6656,3763 ; 6656,3818 6656,3909 ; 6657,3319 6657,3386 ; 6657,3396 6657,3433 ; 6657,3444 6657,3656 ; 6657,3687 6657,3701 ; 6657,3732 6657,3763 ; 6657,3819 6657,3909 ; 6658,3319 6658,3381 ; 6658,3402 6658,3429 ; 6658,3450 6658,3657 ; 6658,3687 6658,3702 ; 6658,3732 6658,3763 ; 6658,3819 6658,3909 ; 6659,3319 6659,3379 ; 6659,3405 6659,3426 ; 6659,3453 6659,3644 ; 6659,3687 6659,3702 ; 6659,3733 6659,3763 ; 6659,3820 6659,3909 ; 6660,3319 6660,3377 ; 6660,3407 6660,3425 ; 6660,3455 6660,3464 ; 6660,3495 6660,3510 ; 6660,3541 6660,3558 ; 6660,3589 6660,3602 ; 6660,3633 6660,3644 ; 6660,3688 6660,3702 ; 6660,3733 6660,3763 ; 6660,3791 6660,3792 ; 6660,3820 6660,3909 ; 6661,3319 6661,3375 ; 6661,3409 6661,3423 ; 6661,3457 6661,3464 ; 6661,3495 6661,3510 ; 6661,3541 6661,3558 ; 6661,3589 6661,3603 ; 6661,3633 6661,3645 ; 6661,3688 6661,3702 ; 6661,3733 6661,3763 ; 6661,3791 6661,3792 ; 6661,3821 6661,3909 ; 6662,3319 6662,3374 ; 6662,3411 6662,3422 ; 6662,3458 6662,3464 ; 6662,3495 6662,3510 ; 6662,3541 6662,3558 ; 6662,3589 6662,3603 ; 6662,3634 6662,3645 ; 6662,3688 6662,3703 ; 6662,3733 6662,3763 ; 6662,3791 6662,3793 ; 6662,3821 6662,3909 ; 6663,3319 6663,3373 ; 6663,3413 6663,3422 ; 6663,3460 6663,3465 ; 6663,3496 6663,3511 ; 6663,3541 6663,3559 ; 6663,3589 6663,3603 ; 6663,3634 6663,3645 ; 6663,3688 6663,3703 ; 6663,3734 6663,3763 ; 6663,3791 6663,3793 ; 6663,3822 6663,3909 ; 6664,3319 6664,3373 ; 6664,3414 6664,3421 ; 6664,3461 6664,3465 ; 6664,3496 6664,3511 ; 6664,3542 6664,3559 ; 6664,3590 6664,3603 ; 6664,3634 6664,3645 ; 6664,3689 6664,3703 ; 6664,3734 6664,3763 ; 6664,3791 6664,3794 ; 6664,3822 6664,3909 ; 6665,3319 6665,3372 ; 6665,3415 6665,3420 ; 6665,3462 6665,3465 ; 6665,3496 6665,3511 ; 6665,3542 6665,3559 ; 6665,3590 6665,3604 ; 6665,3634 6665,3646 ; 6665,3689 6665,3704 ; 6665,3734 6665,3763 ; 6665,3791 6665,3794 ; 6665,3823 6665,3909 ; 6666,3319 6666,3372 ; 6666,3416 6666,3420 ; 6666,3463 6666,3465 ; 6666,3496 6666,3511 ; 6666,3542 6666,3559 ; 6666,3590 6666,3604 ; 6666,3635 6666,3646 ; 6666,3689 6666,3704 ; 6666,3734 6666,3762 ; 6666,3791 6666,3795 ; 6666,3824 6666,3909 ; 6667,3319 6667,3372 ; 6667,3417 6667,3420 ; 6667,3464 6667,3466 ; 6667,3497 6667,3512 ; 6667,3542 6667,3560 ; 6667,3590 6667,3604 ; 6667,3635 6667,3646 ; 6667,3689 6667,3704 ; 6667,3735 6667,3762 ; 6667,3791 6667,3795 ; 6667,3824 6667,3909 ; 6668,3319 6668,3372 ; 6668,3418 6668,3419 ; 6668,3465 6668,3466 ; 6668,3497 6668,3512 ; 6668,3543 6668,3560 ; 6668,3591 6668,3604 ; 6668,3635 6668,3646 ; 6668,3690 6668,3704 ; 6668,3735 6668,3762 ; 6668,3791 6668,3796 ; 6668,3825 6668,3909 ; 6669,3319 6669,3371 ; 6669,3497 6669,3512 ; 6669,3543 6669,3560 ; 6669,3591 6669,3605 ; 6669,3635 6669,3647 ; 6669,3690 6669,3705 ; 6669,3735 6669,3762 ; 6669,3791 6669,3796 ; 6669,3825 6669,3909 ; 6670,3319 6670,3371 ; 6670,3497 6670,3512 ; 6670,3543 6670,3560 ; 6670,3591 6670,3605 ; 6670,3636 6670,3647 ; 6670,3690 6670,3705 ; 6670,3735 6670,3762 ; 6670,3791 6670,3797 ; 6670,3826 6670,3909 ; 6671,3319 6671,3371 ; 6671,3498 6671,3513 ; 6671,3543 6671,3561 ; 6671,3591 6671,3605 ; 6671,3636 6671,3647 ; 6671,3690 6671,3705 ; 6671,3736 6671,3762 ; 6671,3791 6671,3797 ; 6671,3826 6671,3909 ; 6672,3319 6672,3371 ; 6672,3498 6672,3513 ; 6672,3544 6672,3561 ; 6672,3592 6672,3605 ; 6672,3636 6672,3647 ; 6672,3691 6672,3705 ; 6672,3736 6672,3762 ; 6672,3791 6672,3797 ; 6672,3827 6672,3909 ; 6673,3319 6673,3371 ; 6673,3498 6673,3513 ; 6673,3544 6673,3561 ; 6673,3592 6673,3606 ; 6673,3636 6673,3648 ; 6673,3691 6673,3706 ; 6673,3736 6673,3762 ; 6673,3791 6673,3798 ; 6673,3827 6673,3909 ; 6674,3319 6674,3371 ; 6674,3498 6674,3513 ; 6674,3544 6674,3561 ; 6674,3592 6674,3606 ; 6674,3637 6674,3648 ; 6674,3691 6674,3706 ; 6674,3736 6674,3762 ; 6674,3791 6674,3798 ; 6674,3828 6674,3909 ; 6675,3319 6675,3372 ; 6675,3499 6675,3514 ; 6675,3544 6675,3562 ; 6675,3592 6675,3606 ; 6675,3637 6675,3648 ; 6675,3691 6675,3706 ; 6675,3737 6675,3762 ; 6675,3791 6675,3799 ; 6675,3828 6675,3909 ; 6676,3319 6676,3372 ; 6676,3499 6676,3514 ; 6676,3545 6676,3562 ; 6676,3593 6676,3606 ; 6676,3637 6676,3648 ; 6676,3692 6676,3706 ; 6676,3737 6676,3762 ; 6676,3791 6676,3799 ; 6676,3829 6676,3909 ; 6677,3319 6677,3372 ; 6677,3499 6677,3514 ; 6677,3545 6677,3562 ; 6677,3593 6677,3607 ; 6677,3637 6677,3649 ; 6677,3692 6677,3707 ; 6677,3737 6677,3762 ; 6677,3792 6677,3800 ; 6677,3829 6677,3909 ; 6678,3319 6678,3372 ; 6678,3407 6678,3416 ; 6678,3455 6678,3464 ; 6678,3499 6678,3514 ; 6678,3545 6678,3562 ; 6678,3593 6678,3607 ; 6678,3638 6678,3662 ; 6678,3692 6678,3707 ; 6678,3737 6678,3762 ; 6678,3792 6678,3800 ; 6678,3830 6678,3909 ; 6679,3319 6679,3372 ; 6679,3406 6679,3418 ; 6679,3454 6679,3466 ; 6679,3500 6679,3515 ; 6679,3545 6679,3563 ; 6679,3593 6679,3607 ; 6679,3638 6679,3662 ; 6679,3692 6679,3707 ; 6679,3738 6679,3762 ; 6679,3792 6679,3801 ; 6679,3831 6679,3909 ; 6680,3319 6680,3373 ; 6680,3405 6680,3419 ; 6680,3453 6680,3467 ; 6680,3500 6680,3515 ; 6680,3546 6680,3563 ; 6680,3594 6680,3607 ; 6680,3638 6680,3662 ; 6680,3693 6680,3707 ; 6680,3738 6680,3762 ; 6680,3792 6680,3801 ; 6680,3831 6680,3909 ; 6681,3319 6681,3373 ; 6681,3405 6681,3420 ; 6681,3453 6681,3468 ; 6681,3500 6681,3515 ; 6681,3546 6681,3563 ; 6681,3594 6681,3608 ; 6681,3638 6681,3662 ; 6681,3693 6681,3708 ; 6681,3738 6681,3762 ; 6681,3792 6681,3802 ; 6681,3832 6681,3909 ; 6682,3319 6682,3373 ; 6682,3405 6682,3421 ; 6682,3453 6682,3469 ; 6682,3500 6682,3515 ; 6682,3546 6682,3563 ; 6682,3594 6682,3608 ; 6682,3639 6682,3663 ; 6682,3693 6682,3708 ; 6682,3738 6682,3762 ; 6682,3792 6682,3802 ; 6682,3832 6682,3909 ; 6683,3319 6683,3373 ; 6683,3404 6683,3421 ; 6683,3453 6683,3469 ; 6683,3501 6683,3516 ; 6683,3546 6683,3564 ; 6683,3594 6683,3608 ; 6683,3639 6683,3663 ; 6683,3693 6683,3708 ; 6683,3739 6683,3762 ; 6683,3792 6683,3802 ; 6683,3833 6683,3909 ; 6684,3319 6684,3374 ; 6684,3405 6684,3422 ; 6684,3453 6684,3470 ; 6684,3501 6684,3516 ; 6684,3547 6684,3564 ; 6684,3595 6684,3608 ; 6684,3639 6684,3663 ; 6684,3694 6684,3708 ; 6684,3739 6684,3762 ; 6684,3792 6684,3803 ; 6684,3833 6684,3909 ; 6685,3319 6685,3374 ; 6685,3405 6685,3422 ; 6685,3453 6685,3470 ; 6685,3501 6685,3516 ; 6685,3547 6685,3564 ; 6685,3595 6685,3609 ; 6685,3639 6685,3663 ; 6685,3694 6685,3709 ; 6685,3739 6685,3762 ; 6685,3792 6685,3803 ; 6685,3834 6685,3909 ; 6686,3319 6686,3374 ; 6686,3405 6686,3422 ; 6686,3453 6686,3471 ; 6686,3501 6686,3516 ; 6686,3547 6686,3564 ; 6686,3595 6686,3609 ; 6686,3640 6686,3664 ; 6686,3694 6686,3709 ; 6686,3739 6686,3762 ; 6686,3792 6686,3804 ; 6686,3834 6686,3909 ; 6687,3319 6687,3374 ; 6687,3405 6687,3423 ; 6687,3453 6687,3471 ; 6687,3502 6687,3517 ; 6687,3547 6687,3565 ; 6687,3595 6687,3609 ; 6687,3640 6687,3664 ; 6687,3694 6687,3709 ; 6687,3740 6687,3762 ; 6687,3792 6687,3804 ; 6687,3835 6687,3909 ; 6688,3319 6688,3375 ; 6688,3405 6688,3423 ; 6688,3454 6688,3471 ; 6688,3502 6688,3517 ; 6688,3548 6688,3565 ; 6688,3596 6688,3609 ; 6688,3640 6688,3664 ; 6688,3695 6688,3709 ; 6688,3740 6688,3762 ; 6688,3792 6688,3805 ; 6688,3835 6688,3909 ; 6689,3319 6689,3375 ; 6689,3406 6689,3423 ; 6689,3454 6689,3471 ; 6689,3502 6689,3517 ; 6689,3548 6689,3565 ; 6689,3596 6689,3610 ; 6689,3640 6689,3664 ; 6689,3695 6689,3710 ; 6689,3740 6689,3762 ; 6689,3792 6689,3805 ; 6689,3836 6689,3909 ; 6690,3319 6690,3375 ; 6690,3406 6690,3424 ; 6690,3454 6690,3472 ; 6690,3502 6690,3517 ; 6690,3548 6690,3565 ; 6690,3596 6690,3610 ; 6690,3641 6690,3665 ; 6690,3695 6690,3710 ; 6690,3740 6690,3762 ; 6690,3792 6690,3806 ; 6690,3836 6690,3909 ; 6691,3319 6691,3375 ; 6691,3406 6691,3424 ; 6691,3454 6691,3472 ; 6691,3503 6691,3518 ; 6691,3548 6691,3566 ; 6691,3596 6691,3610 ; 6691,3641 6691,3665 ; 6691,3696 6691,3710 ; 6691,3741 6691,3762 ; 6691,3792 6691,3806 ; 6691,3837 6691,3909 ; 6692,3319 6692,3376 ; 6692,3406 6692,3424 ; 6692,3455 6692,3472 ; 6692,3503 6692,3518 ; 6692,3549 6692,3566 ; 6692,3597 6692,3610 ; 6692,3641 6692,3665 ; 6692,3696 6692,3710 ; 6692,3741 6692,3762 ; 6692,3792 6692,3807 ; 6692,3837 6692,3909 ; 6693,3319 6693,3376 ; 6693,3407 6693,3424 ; 6693,3455 6693,3472 ; 6693,3503 6693,3518 ; 6693,3549 6693,3566 ; 6693,3597 6693,3611 ; 6693,3641 6693,3665 ; 6693,3696 6693,3711 ; 6693,3741 6693,3761 ; 6693,3792 6693,3807 ; 6693,3838 6693,3909 ; 6694,3319 6694,3376 ; 6694,3407 6694,3425 ; 6694,3455 6694,3473 ; 6694,3503 6694,3518 ; 6694,3549 6694,3566 ; 6694,3597 6694,3611 ; 6694,3642 6694,3666 ; 6694,3696 6694,3711 ; 6694,3741 6694,3761 ; 6694,3792 6694,3808 ; 6694,3839 6694,3909 ; 6695,3319 6695,3376 ; 6695,3407 6695,3425 ; 6695,3455 6695,3473 ; 6695,3504 6695,3519 ; 6695,3549 6695,3567 ; 6695,3597 6695,3611 ; 6695,3642 6695,3666 ; 6695,3697 6695,3711 ; 6695,3742 6695,3761 ; 6695,3793 6695,3808 ; 6695,3839 6695,3909 ; 6696,3319 6696,3377 ; 6696,3407 6696,3425 ; 6696,3456 6696,3473 ; 6696,3504 6696,3519 ; 6696,3550 6696,3567 ; 6696,3598 6696,3611 ; 6696,3642 6696,3666 ; 6696,3697 6696,3711 ; 6696,3742 6696,3761 ; 6696,3793 6696,3808 ; 6696,3840 6696,3909 ; 6697,3319 6697,3377 ; 6697,3408 6697,3425 ; 6697,3456 6697,3473 ; 6697,3504 6697,3519 ; 6697,3550 6697,3567 ; 6697,3598 6697,3612 ; 6697,3642 6697,3666 ; 6697,3697 6697,3712 ; 6697,3742 6697,3761 ; 6697,3793 6697,3809 ; 6697,3840 6697,3909 ; 6698,3319 6698,3377 ; 6698,3408 6698,3426 ; 6698,3456 6698,3474 ; 6698,3504 6698,3519 ; 6698,3550 6698,3567 ; 6698,3598 6698,3612 ; 6698,3643 6698,3667 ; 6698,3697 6698,3712 ; 6698,3742 6698,3761 ; 6698,3793 6698,3809 ; 6698,3841 6698,3909 ; 6699,3319 6699,3377 ; 6699,3408 6699,3426 ; 6699,3456 6699,3474 ; 6699,3505 6699,3520 ; 6699,3550 6699,3568 ; 6699,3598 6699,3612 ; 6699,3643 6699,3667 ; 6699,3698 6699,3712 ; 6699,3743 6699,3761 ; 6699,3793 6699,3810 ; 6699,3841 6699,3909 ; 6700,3319 6700,3378 ; 6700,3408 6700,3426 ; 6700,3457 6700,3474 ; 6700,3505 6700,3520 ; 6700,3551 6700,3568 ; 6700,3599 6700,3612 ; 6700,3643 6700,3667 ; 6700,3698 6700,3712 ; 6700,3743 6700,3761 ; 6700,3793 6700,3810 ; 6700,3842 6700,3909 ; 6701,3319 6701,3378 ; 6701,3409 6701,3426 ; 6701,3457 6701,3474 ; 6701,3505 6701,3520 ; 6701,3551 6701,3568 ; 6701,3599 6701,3613 ; 6701,3643 6701,3667 ; 6701,3698 6701,3713 ; 6701,3743 6701,3761 ; 6701,3793 6701,3811 ; 6701,3842 6701,3909 ; 6702,3319 6702,3378 ; 6702,3409 6702,3427 ; 6702,3457 6702,3475 ; 6702,3505 6702,3520 ; 6702,3551 6702,3568 ; 6702,3599 6702,3613 ; 6702,3644 6702,3668 ; 6702,3698 6702,3713 ; 6702,3743 6702,3761 ; 6702,3843 6702,3909 ; 6703,3319 6703,3378 ; 6703,3409 6703,3427 ; 6703,3457 6703,3475 ; 6703,3506 6703,3521 ; 6703,3551 6703,3569 ; 6703,3599 6703,3613 ; 6703,3644 6703,3668 ; 6703,3699 6703,3713 ; 6703,3744 6703,3761 ; 6703,3843 6703,3909 ; 6704,3319 6704,3379 ; 6704,3409 6704,3427 ; 6704,3458 6704,3475 ; 6704,3506 6704,3521 ; 6704,3552 6704,3569 ; 6704,3600 6704,3613 ; 6704,3644 6704,3668 ; 6704,3699 6704,3713 ; 6704,3744 6704,3761 ; 6704,3844 6704,3909 ; 6705,3319 6705,3379 ; 6705,3410 6705,3427 ; 6705,3458 6705,3475 ; 6705,3506 6705,3521 ; 6705,3552 6705,3569 ; 6705,3600 6705,3614 ; 6705,3644 6705,3668 ; 6705,3699 6705,3714 ; 6705,3744 6705,3761 ; 6705,3844 6705,3909 ; 6706,3319 6706,3379 ; 6706,3410 6706,3428 ; 6706,3458 6706,3476 ; 6706,3506 6706,3521 ; 6706,3552 6706,3569 ; 6706,3600 6706,3614 ; 6706,3645 6706,3669 ; 6706,3699 6706,3714 ; 6706,3744 6706,3761 ; 6706,3845 6706,3909 ; 6707,3319 6707,3379 ; 6707,3410 6707,3428 ; 6707,3458 6707,3476 ; 6707,3507 6707,3522 ; 6707,3552 6707,3570 ; 6707,3600 6707,3614 ; 6707,3645 6707,3669 ; 6707,3700 6707,3714 ; 6707,3745 6707,3761 ; 6707,3846 6707,3909 ; 6708,3319 6708,3380 ; 6708,3410 6708,3428 ; 6708,3459 6708,3476 ; 6708,3507 6708,3522 ; 6708,3553 6708,3570 ; 6708,3601 6708,3614 ; 6708,3645 6708,3669 ; 6708,3700 6708,3714 ; 6708,3745 6708,3761 ; 6708,3846 6708,3909 ; 6709,3319 6709,3380 ; 6709,3411 6709,3428 ; 6709,3459 6709,3476 ; 6709,3507 6709,3522 ; 6709,3553 6709,3570 ; 6709,3601 6709,3615 ; 6709,3645 6709,3669 ; 6709,3700 6709,3715 ; 6709,3745 6709,3761 ; 6709,3847 6709,3909 ; 6710,3319 6710,3380 ; 6710,3411 6710,3429 ; 6710,3459 6710,3477 ; 6710,3507 6710,3522 ; 6710,3553 6710,3570 ; 6710,3601 6710,3615 ; 6710,3646 6710,3670 ; 6710,3700 6710,3715 ; 6710,3745 6710,3761 ; 6710,3847 6710,3909 ; 6711,3319 6711,3380 ; 6711,3411 6711,3429 ; 6711,3459 6711,3477 ; 6711,3508 6711,3523 ; 6711,3553 6711,3571 ; 6711,3601 6711,3615 ; 6711,3646 6711,3670 ; 6711,3701 6711,3715 ; 6711,3746 6711,3761 ; 6711,3848 6711,3909 ; 6712,3319 6712,3381 ; 6712,3411 6712,3429 ; 6712,3460 6712,3477 ; 6712,3508 6712,3523 ; 6712,3554 6712,3571 ; 6712,3602 6712,3615 ; 6712,3646 6712,3670 ; 6712,3701 6712,3715 ; 6712,3746 6712,3761 ; 6712,3848 6712,3909 ; 6713,3319 6713,3381 ; 6713,3412 6713,3429 ; 6713,3460 6713,3477 ; 6713,3508 6713,3523 ; 6713,3554 6713,3571 ; 6713,3602 6713,3616 ; 6713,3646 6713,3670 ; 6713,3701 6713,3716 ; 6713,3746 6713,3761 ; 6713,3849 6713,3909 ; 6714,3319 6714,3381 ; 6714,3412 6714,3430 ; 6714,3460 6714,3478 ; 6714,3508 6714,3523 ; 6714,3554 6714,3571 ; 6714,3602 6714,3616 ; 6714,3647 6714,3671 ; 6714,3701 6714,3716 ; 6714,3746 6714,3761 ; 6714,3849 6714,3909 ; 6715,3319 6715,3381 ; 6715,3412 6715,3430 ; 6715,3460 6715,3478 ; 6715,3509 6715,3524 ; 6715,3554 6715,3572 ; 6715,3602 6715,3616 ; 6715,3647 6715,3671 ; 6715,3702 6715,3716 ; 6715,3747 6715,3761 ; 6715,3850 6715,3909 ; 6716,3319 6716,3382 ; 6716,3412 6716,3430 ; 6716,3461 6716,3478 ; 6716,3509 6716,3524 ; 6716,3555 6716,3572 ; 6716,3603 6716,3616 ; 6716,3647 6716,3671 ; 6716,3702 6716,3716 ; 6716,3747 6716,3761 ; 6716,3850 6716,3909 ; 6717,3319 6717,3382 ; 6717,3413 6717,3430 ; 6717,3461 6717,3478 ; 6717,3509 6717,3524 ; 6717,3555 6717,3572 ; 6717,3603 6717,3617 ; 6717,3647 6717,3671 ; 6717,3702 6717,3717 ; 6717,3747 6717,3761 ; 6717,3851 6717,3909 ; 6718,3319 6718,3382 ; 6718,3413 6718,3431 ; 6718,3461 6718,3479 ; 6718,3509 6718,3524 ; 6718,3556 6718,3572 ; 6718,3603 6718,3617 ; 6718,3648 6718,3671 ; 6718,3702 6718,3717 ; 6718,3747 6718,3761 ; 6718,3851 6718,3909 ; 6719,3319 6719,3382 ; 6719,3413 6719,3431 ; 6719,3461 6719,3479 ; 6719,3510 6719,3525 ; 6719,3556 6719,3572 ; 6719,3603 6719,3617 ; 6719,3648 6719,3672 ; 6719,3703 6719,3717 ; 6719,3748 6719,3760 ; 6719,3852 6719,3909 ; 6720,3319 6720,3383 ; 6720,3413 6720,3431 ; 6720,3462 6720,3479 ; 6720,3510 6720,3525 ; 6720,3557 6720,3571 ; 6720,3604 6720,3617 ; 6720,3648 6720,3671 ; 6720,3703 6720,3717 ; 6720,3748 6720,3760 ; 6720,3852 6720,3909 ; 6721,3319 6721,3383 ; 6721,3414 6721,3431 ; 6721,3462 6721,3479 ; 6721,3510 6721,3525 ; 6721,3558 6721,3571 ; 6721,3604 6721,3618 ; 6721,3648 6721,3671 ; 6721,3703 6721,3718 ; 6721,3748 6721,3760 ; 6721,3853 6721,3909 ; 6722,3319 6722,3383 ; 6722,3414 6722,3432 ; 6722,3462 6722,3480 ; 6722,3510 6722,3525 ; 6722,3560 6722,3570 ; 6722,3604 6722,3618 ; 6722,3649 6722,3670 ; 6722,3703 6722,3718 ; 6722,3748 6722,3760 ; 6722,3854 6722,3909 ; 6723,3319 6723,3383 ; 6723,3414 6723,3432 ; 6723,3462 6723,3480 ; 6723,3511 6723,3526 ; 6723,3604 6723,3618 ; 6723,3649 6723,3660 ; 6723,3704 6723,3718 ; 6723,3749 6723,3760 ; 6723,3794 6723,3820 ; 6723,3854 6723,3909 ; 6724,3319 6724,3384 ; 6724,3414 6724,3432 ; 6724,3463 6724,3480 ; 6724,3511 6724,3526 ; 6724,3605 6724,3618 ; 6724,3649 6724,3660 ; 6724,3704 6724,3718 ; 6724,3749 6724,3760 ; 6724,3794 6724,3821 ; 6724,3855 6724,3909 ; 6725,3319 6725,3384 ; 6725,3415 6725,3432 ; 6725,3463 6725,3480 ; 6725,3511 6725,3526 ; 6725,3605 6725,3619 ; 6725,3649 6725,3661 ; 6725,3704 6725,3719 ; 6725,3749 6725,3760 ; 6725,3794 6725,3821 ; 6725,3855 6725,3909 ; 6726,3319 6726,3384 ; 6726,3415 6726,3433 ; 6726,3463 6726,3481 ; 6726,3511 6726,3526 ; 6726,3605 6726,3619 ; 6726,3650 6726,3661 ; 6726,3704 6726,3719 ; 6726,3749 6726,3760 ; 6726,3794 6726,3822 ; 6726,3856 6726,3909 ; 6727,3319 6727,3384 ; 6727,3415 6727,3433 ; 6727,3463 6727,3481 ; 6727,3512 6727,3527 ; 6727,3605 6727,3619 ; 6727,3650 6727,3661 ; 6727,3704 6727,3719 ; 6727,3750 6727,3760 ; 6727,3794 6727,3822 ; 6727,3856 6727,3909 ; 6728,3319 6728,3385 ; 6728,3415 6728,3433 ; 6728,3464 6728,3481 ; 6728,3512 6728,3527 ; 6728,3605 6728,3619 ; 6728,3650 6728,3661 ; 6728,3704 6728,3719 ; 6728,3750 6728,3760 ; 6728,3794 6728,3823 ; 6728,3857 6728,3909 ; 6729,3319 6729,3385 ; 6729,3416 6729,3433 ; 6729,3464 6729,3481 ; 6729,3512 6729,3527 ; 6729,3605 6729,3620 ; 6729,3650 6729,3662 ; 6729,3704 6729,3720 ; 6729,3750 6729,3760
